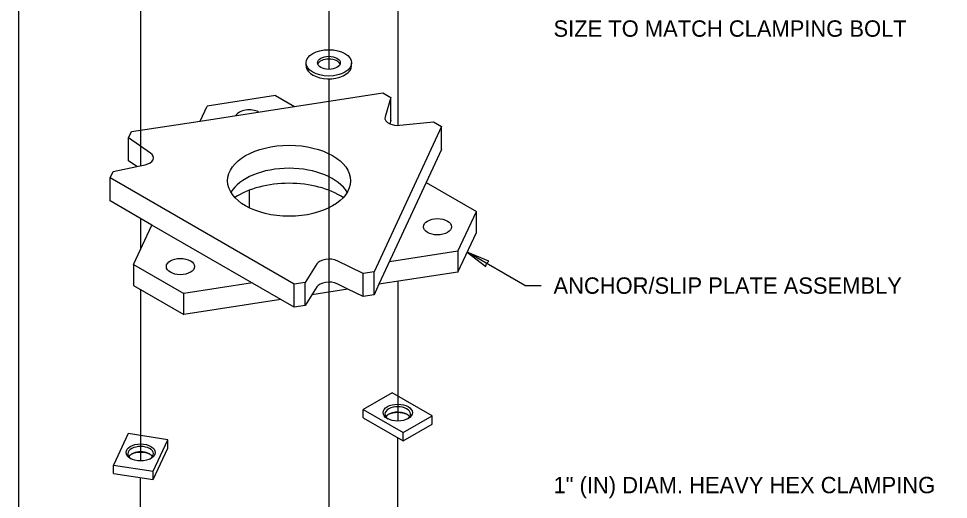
# Model space of a CAD drawing. Extents: x 99862 to 104211, y 98939 to 102076.
# Drawn here: x 99862 to 100770, y 100594 to 101063 of the extents above; entities that cross this region are included whole.
import ezdxf

# ---------------------------------------------------------------- set-up
doc = ezdxf.new("R2010")
doc.units = 0
for name, color, linetype in [('Level 1', 7, 'Continuous'), ('Level 11', 7, 'Continuous'), ('Level 15', 7, 'Continuous'), ('Level 20', 7, 'Continuous'), ('Level 3', 7, 'Continuous'), ('Level 4', 7, 'Continuous'), ('Level 6', 7, 'Continuous'), ('Level 9', 7, 'Continuous')]:
    doc.layers.add(name, color=color, linetype=linetype)

msp = doc.modelspace()

# ---------------------------------------------------------------- linework, layer by layer
at = {"layer": 'Level 1'}
msp.add_lwpolyline([(99862, 99999.5), (103151, 99999.5), (103151, 102075.5), (99862, 102075.5)], close=True, dxfattribs=at)
at = {"layer": 'Level 11'}
for p, q in [((100226.82, 100698.38), (100198.53, 100682.05)), ((100265.71, 100675.93), (100226.82, 100698.38)), ((100198.53, 100673.89), (100198.53, 100682.05)), ((100198.53, 100682.05), (100237.42, 100659.6)), ((100223.28, 100677.37), (100223.28, 100677.37)), ((100237.42, 100659.6), (100265.71, 100675.93)), ((100240.96, 100677.37), (100240.96, 100677.37)), ((100265.71, 100667.76), (100265.71, 100675.93)), ((100198.53, 100673.89), (100237.42, 100651.43)), ((100237.42, 100651.43), (100265.71, 100667.76)), ((99968.96, 100658.49), (99954.73, 100627.82)), ((100007.6, 100652.51), (99968.96, 100658.49)), ((100237.42, 100651.43), (100237.42, 100659.6)), ((99993.37, 100621.84), (100007.6, 100652.51)), ((100007.6, 100644.35), (100007.6, 100652.51)), ((99993.37, 100613.68), (100007.6, 100644.35)), ((99971.08, 100634.34), (99971.08, 100634.34)), ((99990, 100638.55), (99990, 100638.55)), ((99991.25, 100634.34), (99991.25, 100634.34)), ((99954.73, 100619.65), (99954.73, 100627.82)), ((99954.73, 100627.82), (99993.37, 100621.84)), ((99993.37, 100613.68), (99993.37, 100621.84)), ((99954.73, 100619.65), (99993.37, 100613.68))]:
    msp.add_line(p, q, dxfattribs=at)
for centre, major_axis in [((100232.12, 100678.99), (-14.27, 0)), ((99981.16, 100640.17), (14.27, 0))]:
    msp.add_ellipse(centre, major_axis=major_axis, ratio=0.57735, dxfattribs=at)
for centre, major_axis, start_param, end_param in [((100232.12, 100677.55), (-12.5, 0), 2.424619, 7.000159), ((100232.12, 100672.27), (-12.5, 0), 3.927, 5.908816), ((100232.12, 100670.82), (-14.27, 0), 3.991034, 5.433744), ((100232.12, 100672.27), (-12.5, 0), 3.515962, 3.927), ((99981.16, 100638.72), (12.5, 0), 5.566211, 10.141752), ((99981.16, 100633.45), (12.5, 0), 0.374369, 2.767224), ((99981.16, 100632), (14.27, 0), 0.849442, 2.292151)]:
    msp.add_ellipse(centre, major_axis=major_axis, ratio=0.57735, start_param=start_param, end_param=end_param, dxfattribs=at)
at = {"layer": 'Level 15'}
for q in [(100299.92, 100835.43), (100372.21, 100802.93)]:
    msp.add_line((100356.21, 100802.93), q, dxfattribs=at)
msp.add_lwpolyline([(100299.92, 100835.43), (100318.2, 100821.43), (100318.78, 100824.55), (100321.18, 100826.6)], close=True, dxfattribs=at)
at = {"layer": 'Level 3'}
for p, q in [((100112.93, 100988.3), (100046.01, 100977.95)), ((100112.93, 100988.3), (100131.24, 100977.73)), ((100039.3, 100963.5), (100046.01, 100977.95)), ((100259.9, 100903.45), (100308.89, 100875.17)), ((100290.95, 100836.53), (100308.89, 100875.17)), ((100308.89, 100854.75), (100308.89, 100875.17)), ((99974.28, 100823.4), (99992.21, 100862.04)), ((100290.95, 100816.12), (100308.89, 100854.75)), ((100290.95, 100836.53), (100224.03, 100826.18)), ((100290.95, 100836.53), (100290.95, 100816.12)), ((99974.28, 100823.4), (99974.28, 100802.99)), ((99974.28, 100823.4), (100023.27, 100795.12)), ((100290.95, 100816.12), (100213.83, 100804.18)), ((99974.28, 100802.99), (100023.27, 100774.7)), ((100090.19, 100805.47), (100023.27, 100795.12)), ((100023.27, 100774.7), (100023.27, 100795.12)), ((100183.54, 100799.5), (100148.36, 100794.06)), ((100118.07, 100789.37), (100023.27, 100774.7))]:
    msp.add_line(p, q, dxfattribs=at)
for centre, major_axis, start_param, end_param in [((100087.23, 100966.4), (-13.75, 0), 3.986035, 5.962342), ((100126.05, 100862.33), (-70, 0), 3.8563, 5.568478)]:
    msp.add_ellipse(centre, major_axis=major_axis, ratio=0.57735, start_param=start_param, end_param=end_param, dxfattribs=at)
for centre in [(100270.94, 100860.33), (100019.99, 100821.51)]:
    msp.add_ellipse(centre, major_axis=(-13.75, 0), ratio=0.57735, dxfattribs=at)
at = {"layer": 'Level 4'}
for p, q in [((100131.24, 100977.73), (100217.68, 100991.1)), ((100217.68, 100991.1), (100225.49, 100986.59)), ((100225.49, 100986.59), (100219.8, 100967.67)), ((100225.49, 100964.14), (100225.49, 100986.59)), ((100039.3, 100963.5), (100131.24, 100977.73)), ((99972.31, 100953.14), (100039.3, 100963.5)), ((100274.84, 100958.1), (100209.09, 100816.43)), ((100225.49, 100964.14), (100224.46, 100960.73)), ((100234.25, 100959.32), (100267.04, 100962.6)), ((100267.04, 100962.6), (100274.84, 100958.1)), ((100274.84, 100935.65), (100274.84, 100958.1)), ((99969.45, 100946.99), (99972.31, 100953.14)), ((99990.76, 100932.23), (99969.45, 100946.99)), ((99969.45, 100924.53), (99969.45, 100946.99)), ((100274.84, 100935.65), (100259.9, 100903.45)), ((99977.29, 100919.1), (99969.45, 100924.53)), ((99977.29, 100919.1), (99985.47, 100920.84)), ((99951.39, 100908.06), (99954.24, 100914.22)), ((99954.24, 100914.22), (99977.29, 100919.1)), ((99951.39, 100885.61), (99951.39, 100908.06)), ((100131.02, 100804.35), (99951.39, 100908.06)), ((100259.9, 100903.45), (100213.83, 100804.18)), ((99992.21, 100862.04), (99951.39, 100885.61)), ((100118.07, 100789.37), (99992.21, 100862.04)), ((100153.14, 100824.03), (100141.67, 100806)), ((100198.43, 100814.78), (100172.88, 100827.09)), ((100209.09, 100816.43), (100198.43, 100814.78)), ((100198.43, 100792.33), (100198.43, 100814.78)), ((100209.09, 100793.98), (100209.09, 100816.43)), ((100141.67, 100806), (100131.02, 100804.35)), ((100131.02, 100781.9), (100131.02, 100804.35)), ((100141.67, 100783.55), (100141.67, 100806)), ((100183.54, 100799.5), (100172.88, 100804.63)), ((100213.83, 100804.18), (100209.09, 100793.98)), ((100148.36, 100794.06), (100141.67, 100783.55)), ((100153.14, 100801.58), (100148.36, 100794.06)), ((100198.43, 100792.33), (100183.54, 100799.5)), ((100209.09, 100793.98), (100198.43, 100792.33)), ((100131.02, 100781.9), (100118.07, 100789.37)), ((100141.67, 100783.55), (100131.02, 100781.9))]:
    msp.add_line(p, q, dxfattribs=at)
for centre, major_axis, start_param, end_param in [((100232.12, 100966.43), (12.5, 0), 2.969943, 4.053067), ((100232.12, 100966.43), (12.5, 0), 4.053067, 4.884038), ((99981.16, 100927.61), (12.5, 0), 5.064338, 6.978434), ((100126.05, 100882.74), (-60, 0), 3.471643, 5.953135), ((100164.88, 100821.55), (12.5, 0), 0.875548, 2.789643), ((100164.88, 100799.09), (12.5, 0), 0.875548, 2.789643)]:
    msp.add_ellipse(centre, major_axis=major_axis, ratio=0.57735, start_param=start_param, end_param=end_param, dxfattribs=at)
msp.add_ellipse((100126.05, 100905.2), major_axis=(-60, 0), ratio=0.57735, dxfattribs=at)
at = {"layer": 'Level 6'}
for p, q in [((100164.88, 101187.9), (100164.88, 101013.81)), ((100232.12, 101149.57), (100232.12, 100959.11)), ((99981.16, 101110.74), (99981.16, 100919.92)), ((100087.23, 100895.96), (100087.23, 100878.79)), ((99981.16, 100868.42), (99981.16, 100838.24)), ((100232.12, 100562.04), (100232.12, 100654.49)), ((99981.16, 100523.22), (99981.16, 100615.56))]:
    msp.add_line(p, q, dxfattribs=at)
for points in [[(100164.88, 101004.68), (100164.88, 100525.86)], [(100232.12, 100807.01), (100232.12, 100670.75)], [(99981.16, 100799.01), (99981.16, 100631.93)]]:
    msp.add_lwpolyline(points, dxfattribs=at)
at = {"layer": 'Level 9'}
for p, q in [((100142.66, 101017.51), (100142.66, 101020.23)), ((100187.1, 101017.51), (100187.1, 101020.23))]:
    msp.add_line(p, q, dxfattribs=at)
for major_axis in [(-22.22, 0), (-11.13, 0)]:
    msp.add_ellipse((100164.88, 101020.23), major_axis=major_axis, ratio=0.57735, dxfattribs=at)
for major_axis, start_param, end_param in [((-11.13, 0), 3.355069, 6.069709), ((-22.22, 0), 6.283185, 6.544985), ((-22.22, 0), 0.261799, 3.141593)]:
    msp.add_ellipse((100164.88, 101017.51), major_axis=major_axis, ratio=0.57735, start_param=start_param, end_param=end_param, dxfattribs=at)

# ---------------------------------------------------------------- texts
at = {"layer": 'Level 20'}
for s, p in [('SIZE TO MATCH CLAMPING BOLT', (100384.21, 101045.69)), ('1" (IN) DIAM. HEAVY HEX CLAMPING ', (100384.21, 100600.32))]:
    msp.add_text(s, height=16, dxfattribs=at).set_placement(p)
msp.add_text('ANCHOR/SLIP PLATE ASSEMBLY', height=16, rotation=360, dxfattribs=at).set_placement((100384.21, 100794.93))

doc.saveas('drawing.dxf')
